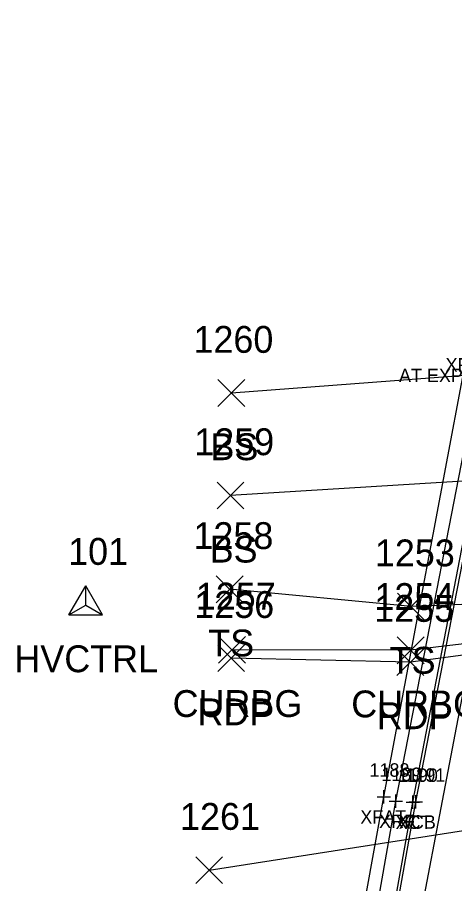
# Model space of a CAD drawing. Extents: x 1683147 to 1683637, y 416837 to 418211.
# Drawn here: x 1683191.9 to 1683224.4, y 417543.9 to 417608.4 of the extents above; entities that cross this region are included whole.
import ezdxf

# ---------------------------------------------------------------- set-up
doc = ezdxf.new("R2010")
doc.units = 0
for name, color, linetype in [('B_A', 7, 'Continuous'), ('B_C', 7, 'Continuous'), ('B_I', 7, 'Continuous'), ('B_TIC', 7, 'Continuous'), ('BB', 7, 'Continuous'), ('BDC', 7, 'Continuous'), ('BF', 7, 'Continuous'), ('BR', 7, 'Continuous'), ('C_A', 7, 'Continuous'), ('C_I', 7, 'Continuous'), ('CPSM', 7, 'Continuous'), ('L_A', 7, 'Continuous'), ('L_I', 7, 'Continuous'), ('L_TIC', 7, 'Continuous'), ('LELB', 7, 'Continuous'), ('P_A', 7, 'Continuous'), ('P_I', 7, 'Continuous'), ('P_TIC', 7, 'Continuous'), ('PET', 7, 'Continuous'), ('PRC', 7, 'Continuous'), ('R_A', 7, 'Continuous'), ('R_I', 7, 'Continuous'), ('R_TIC', 7, 'Continuous'), ('RC', 7, 'Continuous')]:
    doc.layers.add(name, color=color, linetype=linetype)

msp = doc.modelspace()

# ---------------------------------------------------------------- linework, layer by layer
at = {"layer": 'B_TIC'}
for p, q in [((1683219.152, 417550.319), (1683219.228, 417550.319)), ((1683220.045, 417550.002), (1683220.121, 417550.002)), ((1683221.314, 417549.93), (1683221.39, 417549.93)), ((1683221.546, 417549.946), (1683221.621, 417549.946))]:
    msp.add_line(p, q, dxfattribs=at)
for points in [[(1683219.149, 417549.819), (1683219.149, 417550.819)], [(1683218.649, 417550.319), (1683219.649, 417550.319)], [(1683220.042, 417549.502), (1683220.042, 417550.502)], [(1683221.311, 417549.43), (1683221.311, 417550.43)], [(1683221.542, 417549.446), (1683221.542, 417550.446)], [(1683219.542, 417550.002), (1683220.542, 417550.002)], [(1683220.811, 417549.93), (1683221.811, 417549.93)], [(1683221.042, 417549.946), (1683222.042, 417549.946)]]:
    msp.add_lwpolyline(points, dxfattribs=at)
at = {"layer": 'BB'}
msp.add_lwpolyline([(1683204.248, 417448.864), (1683213.453, 417497.213), (1683232.034, 417594.621), (1683241.123, 417643.096)], dxfattribs=at)
at = {"layer": 'BDC'}
for points in [[(1683204.26, 417446.59), (1683207.746, 417469.989), (1683213.462, 417505.801), (1683221.311, 417549.93), (1683228.046, 417584.722), (1683234.074, 417613.621), (1683241.065, 417645.18)], [(1683204.523, 417446.635), (1683207.943, 417470.136), (1683213.692, 417505.86), (1683221.542, 417549.946), (1683228.342, 417584.807), (1683234.248, 417613.515), (1683241.392, 417644.923)]]:
    msp.add_lwpolyline(points, dxfattribs=at)
at = {"layer": 'BF'}
msp.add_lwpolyline([(1683201.852, 417446.968), (1683205.241, 417469.957), (1683210.957, 417505.098), (1683219.149, 417550.319), (1683225.494, 417584.011), (1683231.655, 417613.999), (1683238.79, 417645.736)], dxfattribs=at)
at = {"layer": 'BR'}
msp.add_lwpolyline([(1683201.249, 417434.944), (1683203.019, 417446.95), (1683206.413, 417469.882), (1683212.207, 417505.421), (1683220.042, 417550.002), (1683226.73, 417584.319), (1683232.917, 417613.974), (1683239.772, 417645.191), (1683242.155, 417655.448)], dxfattribs=at)
at = {"layer": 'CPSM'}
for p, q in [((1683195.705, 417563.886), (1683196.955, 417566.051)), ((1683198.205, 417563.886), (1683196.955, 417566.051)), ((1683196.955, 417564.607), (1683196.955, 417566.051)), ((1683195.705, 417563.886), (1683196.955, 417564.607)), ((1683196.955, 417564.607), (1683196.955, 417564.607)), ((1683196.955, 417564.607), (1683198.205, 417563.886)), ((1683195.705, 417563.886), (1683198.205, 417563.886))]:
    msp.add_line(p, q, dxfattribs=at)
at = {"layer": 'L_TIC'}
for points in [[(1683206.806, 417579.406), (1683208.806, 417581.406)], [(1683208.806, 417579.406), (1683206.806, 417581.406)], [(1683206.744, 417571.779), (1683208.744, 417573.779)], [(1683208.744, 417571.779), (1683206.744, 417573.779)], [(1683206.672, 417564.784), (1683208.672, 417566.784)], [(1683208.672, 417564.784), (1683206.672, 417566.784)], [(1683220.182, 417563.496), (1683222.182, 417565.496)], [(1683222.182, 417563.496), (1683220.182, 417565.496)]]:
    msp.add_lwpolyline(points, dxfattribs=at)
at = {"layer": 'LELB'}
for points in [[(1683285.091, 417588.015), (1683258.675, 417584.256), (1683207.806, 417580.406)], [(1683286.499, 417582.7), (1683258.094, 417575.88), (1683207.744, 417572.779)], [(1683266.126, 417570.722), (1683241.357, 417565.306), (1683221.182, 417564.496), (1683207.672, 417565.784)]]:
    msp.add_lwpolyline(points, dxfattribs=at)
at = {"layer": 'P_TIC'}
for points in [[(1683206.789, 417559.65), (1683208.789, 417561.65)], [(1683208.789, 417559.65), (1683206.789, 417561.65)], [(1683220.134, 417559.361), (1683222.134, 417561.361)], [(1683222.134, 417559.361), (1683220.134, 417561.361)], [(1683205.154, 417543.862), (1683207.154, 417545.862)], [(1683207.154, 417543.862), (1683205.154, 417545.862)]]:
    msp.add_lwpolyline(points, dxfattribs=at)
at = {"layer": 'PET'}
msp.add_lwpolyline([(1683444.524, 417639.397), (1683404.458, 417622.242), (1683363.803, 417604.981), (1683316.848, 417587.705), (1683293.07, 417578.551), (1683271.475, 417569.828), (1683261.715, 417567.454), (1683241.63, 417563.083), (1683221.134, 417560.361), (1683207.789, 417560.65)], dxfattribs=at)
at = {"layer": 'PRC'}
msp.add_lwpolyline([(1683206.154, 417544.862), (1683241.64, 417550.402), (1683274.909, 417557.18), (1683311.228, 417567.333), (1683337.826, 417576.227), (1683364.361, 417586.18)], dxfattribs=at)
at = {"layer": 'R_TIC'}
for points in [[(1683206.845, 417560.271), (1683208.845, 417562.271)], [(1683208.845, 417560.271), (1683206.845, 417562.271)], [(1683220.147, 417560.243), (1683222.147, 417562.243)], [(1683222.147, 417560.243), (1683220.147, 417562.243)]]:
    msp.add_lwpolyline(points, dxfattribs=at)
at = {"layer": 'RC'}
msp.add_lwpolyline([(1683271.475, 417569.828), (1683261.694, 417567.834), (1683241.458, 417563.668), (1683221.147, 417561.243), (1683207.845, 417561.271)], dxfattribs=at)

# ---------------------------------------------------------------- texts
at = {"layer": 'B_A'}
for s, p in [('XFAT', (1683223.75, 417582.011)), ('XFAT', (1683217.405, 417548.319)), ('XRF', (1683218.802, 417548.002)), ('XCT', (1683220.031, 417547.93)), ('XCB', (1683220.278, 417547.946))]:
    msp.add_text(s, height=1, dxfattribs=at).set_placement(p)
at = {"layer": 'B_C'}
msp.add_text('AT EXPANSION JOINT', height=1, dxfattribs=at).set_placement((1683220.286, 417581.222))
at = {"layer": 'B_I'}
for s, p in [('1188', (1683218.086, 417551.819)), ('1189', (1683218.975, 417551.502)), ('1190', (1683220.205, 417551.43)), ('1191', (1683220.763, 417551.446))]:
    msp.add_text(s, height=1, dxfattribs=at).set_placement(p)
at = {"layer": 'C_A'}
msp.add_text('HVCTRL', height=2, dxfattribs=at).set_placement((1683191.648, 417559.607))
at = {"layer": 'C_I'}
msp.add_text('101', height=2, dxfattribs=at).set_placement((1683195.648, 417567.607))
at = {"layer": 'L_A'}
for s, p in [('BS', (1683206.247, 417575.406)), ('BS', (1683206.185, 417567.779)), ('TS', (1683206.082, 417560.784)), ('TS', (1683219.591, 417559.496))]:
    msp.add_text(s, height=2, dxfattribs=at).set_placement(p)
at = {"layer": 'L_I'}
for s, p in [('1260', (1683204.98, 417583.406)), ('1259', (1683205.043, 417575.779)), ('1258', (1683204.979, 417568.784)), ('1253', (1683218.489, 417567.496))]:
    msp.add_text(s, height=2, dxfattribs=at).set_placement(p)
at = {"layer": 'P_A'}
for p in [(1683205.277, 417555.65), (1683218.622, 417555.361)]:
    msp.add_text('RDP', height=2, dxfattribs=at).set_placement(p)
at = {"layer": 'P_I'}
for s, p in [('1256', (1683205.041, 417563.65)), ('1255', (1683218.441, 417563.361)), ('1261', (1683203.981, 417547.862))]:
    msp.add_text(s, height=2, dxfattribs=at).set_placement(p)
at = {"layer": 'R_A'}
for p in [(1683203.428, 417556.271), (1683216.73, 417556.243)]:
    msp.add_text('CURBG', height=2, dxfattribs=at).set_placement(p)
at = {"layer": 'R_I'}
for s, p in [('1257', (1683205.153, 417564.271)), ('1254', (1683218.454, 417564.243))]:
    msp.add_text(s, height=2, dxfattribs=at).set_placement(p)

doc.saveas('drawing.dxf')
